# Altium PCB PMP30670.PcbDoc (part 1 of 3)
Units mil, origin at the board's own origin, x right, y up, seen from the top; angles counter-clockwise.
Board outline 5900 x 3950 mil, 4 copper layers (Top Layer, GND, Signal Layer, Bottom Layer), stack 79.834 mil thick; 198 components, 106 nets, 638 pads, 723 vias.
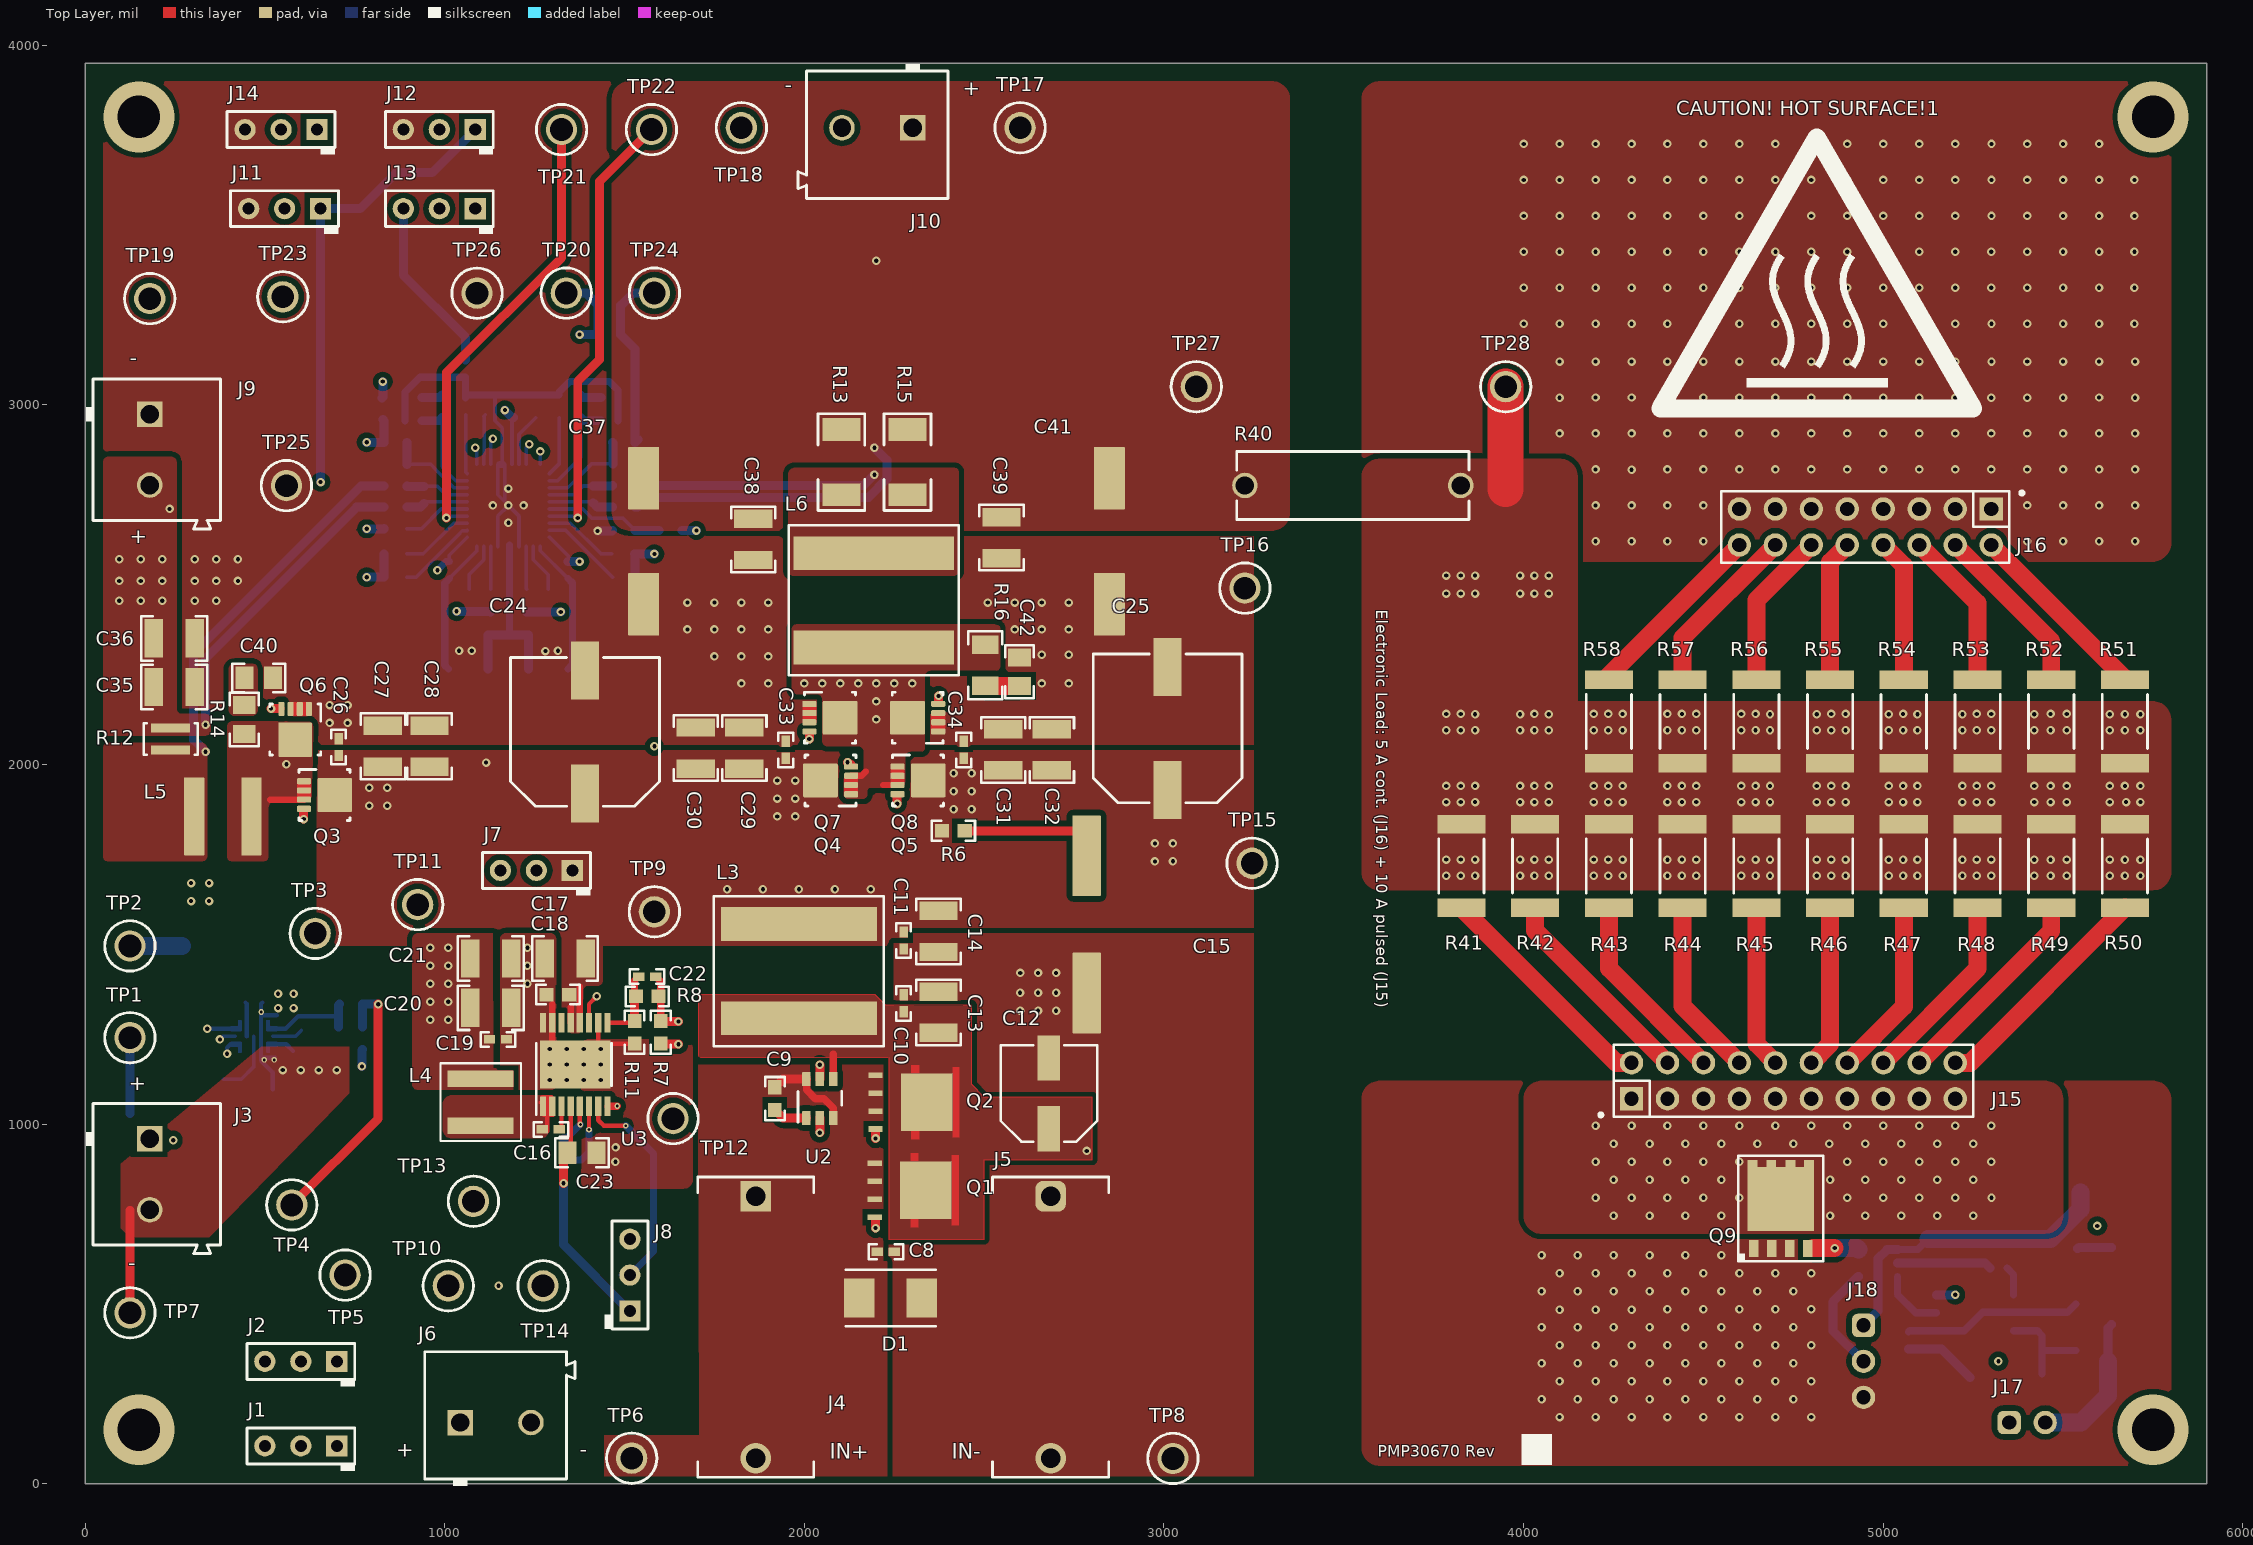
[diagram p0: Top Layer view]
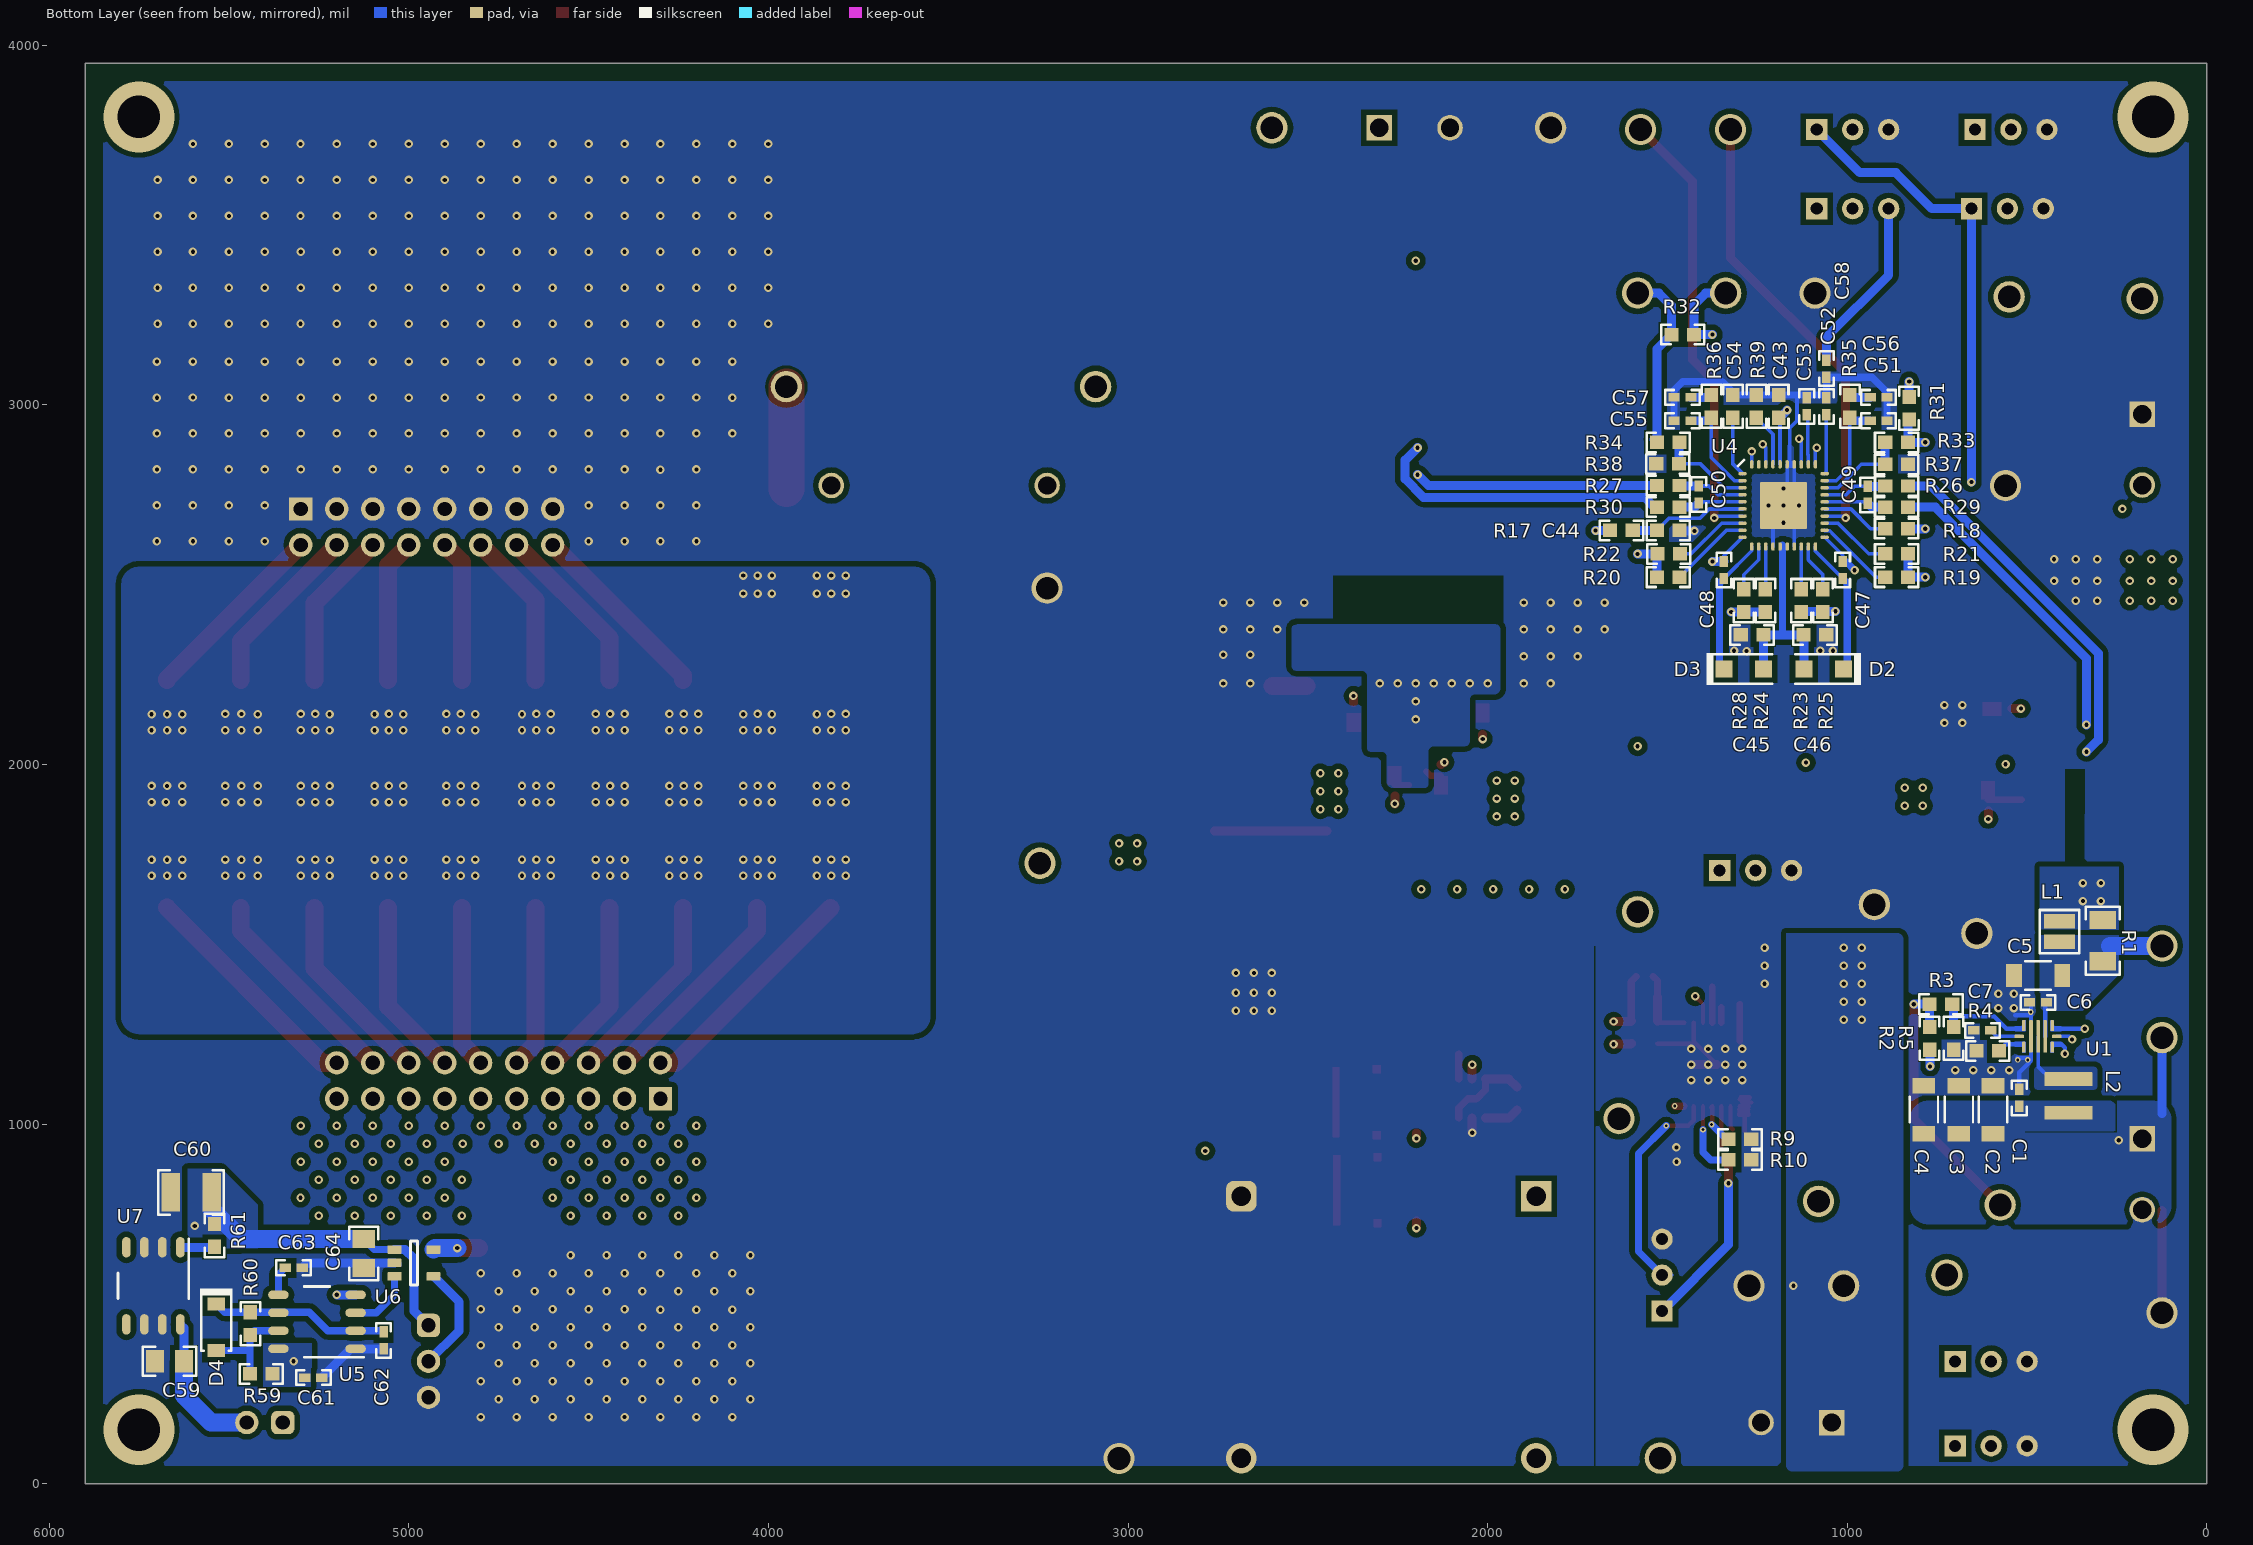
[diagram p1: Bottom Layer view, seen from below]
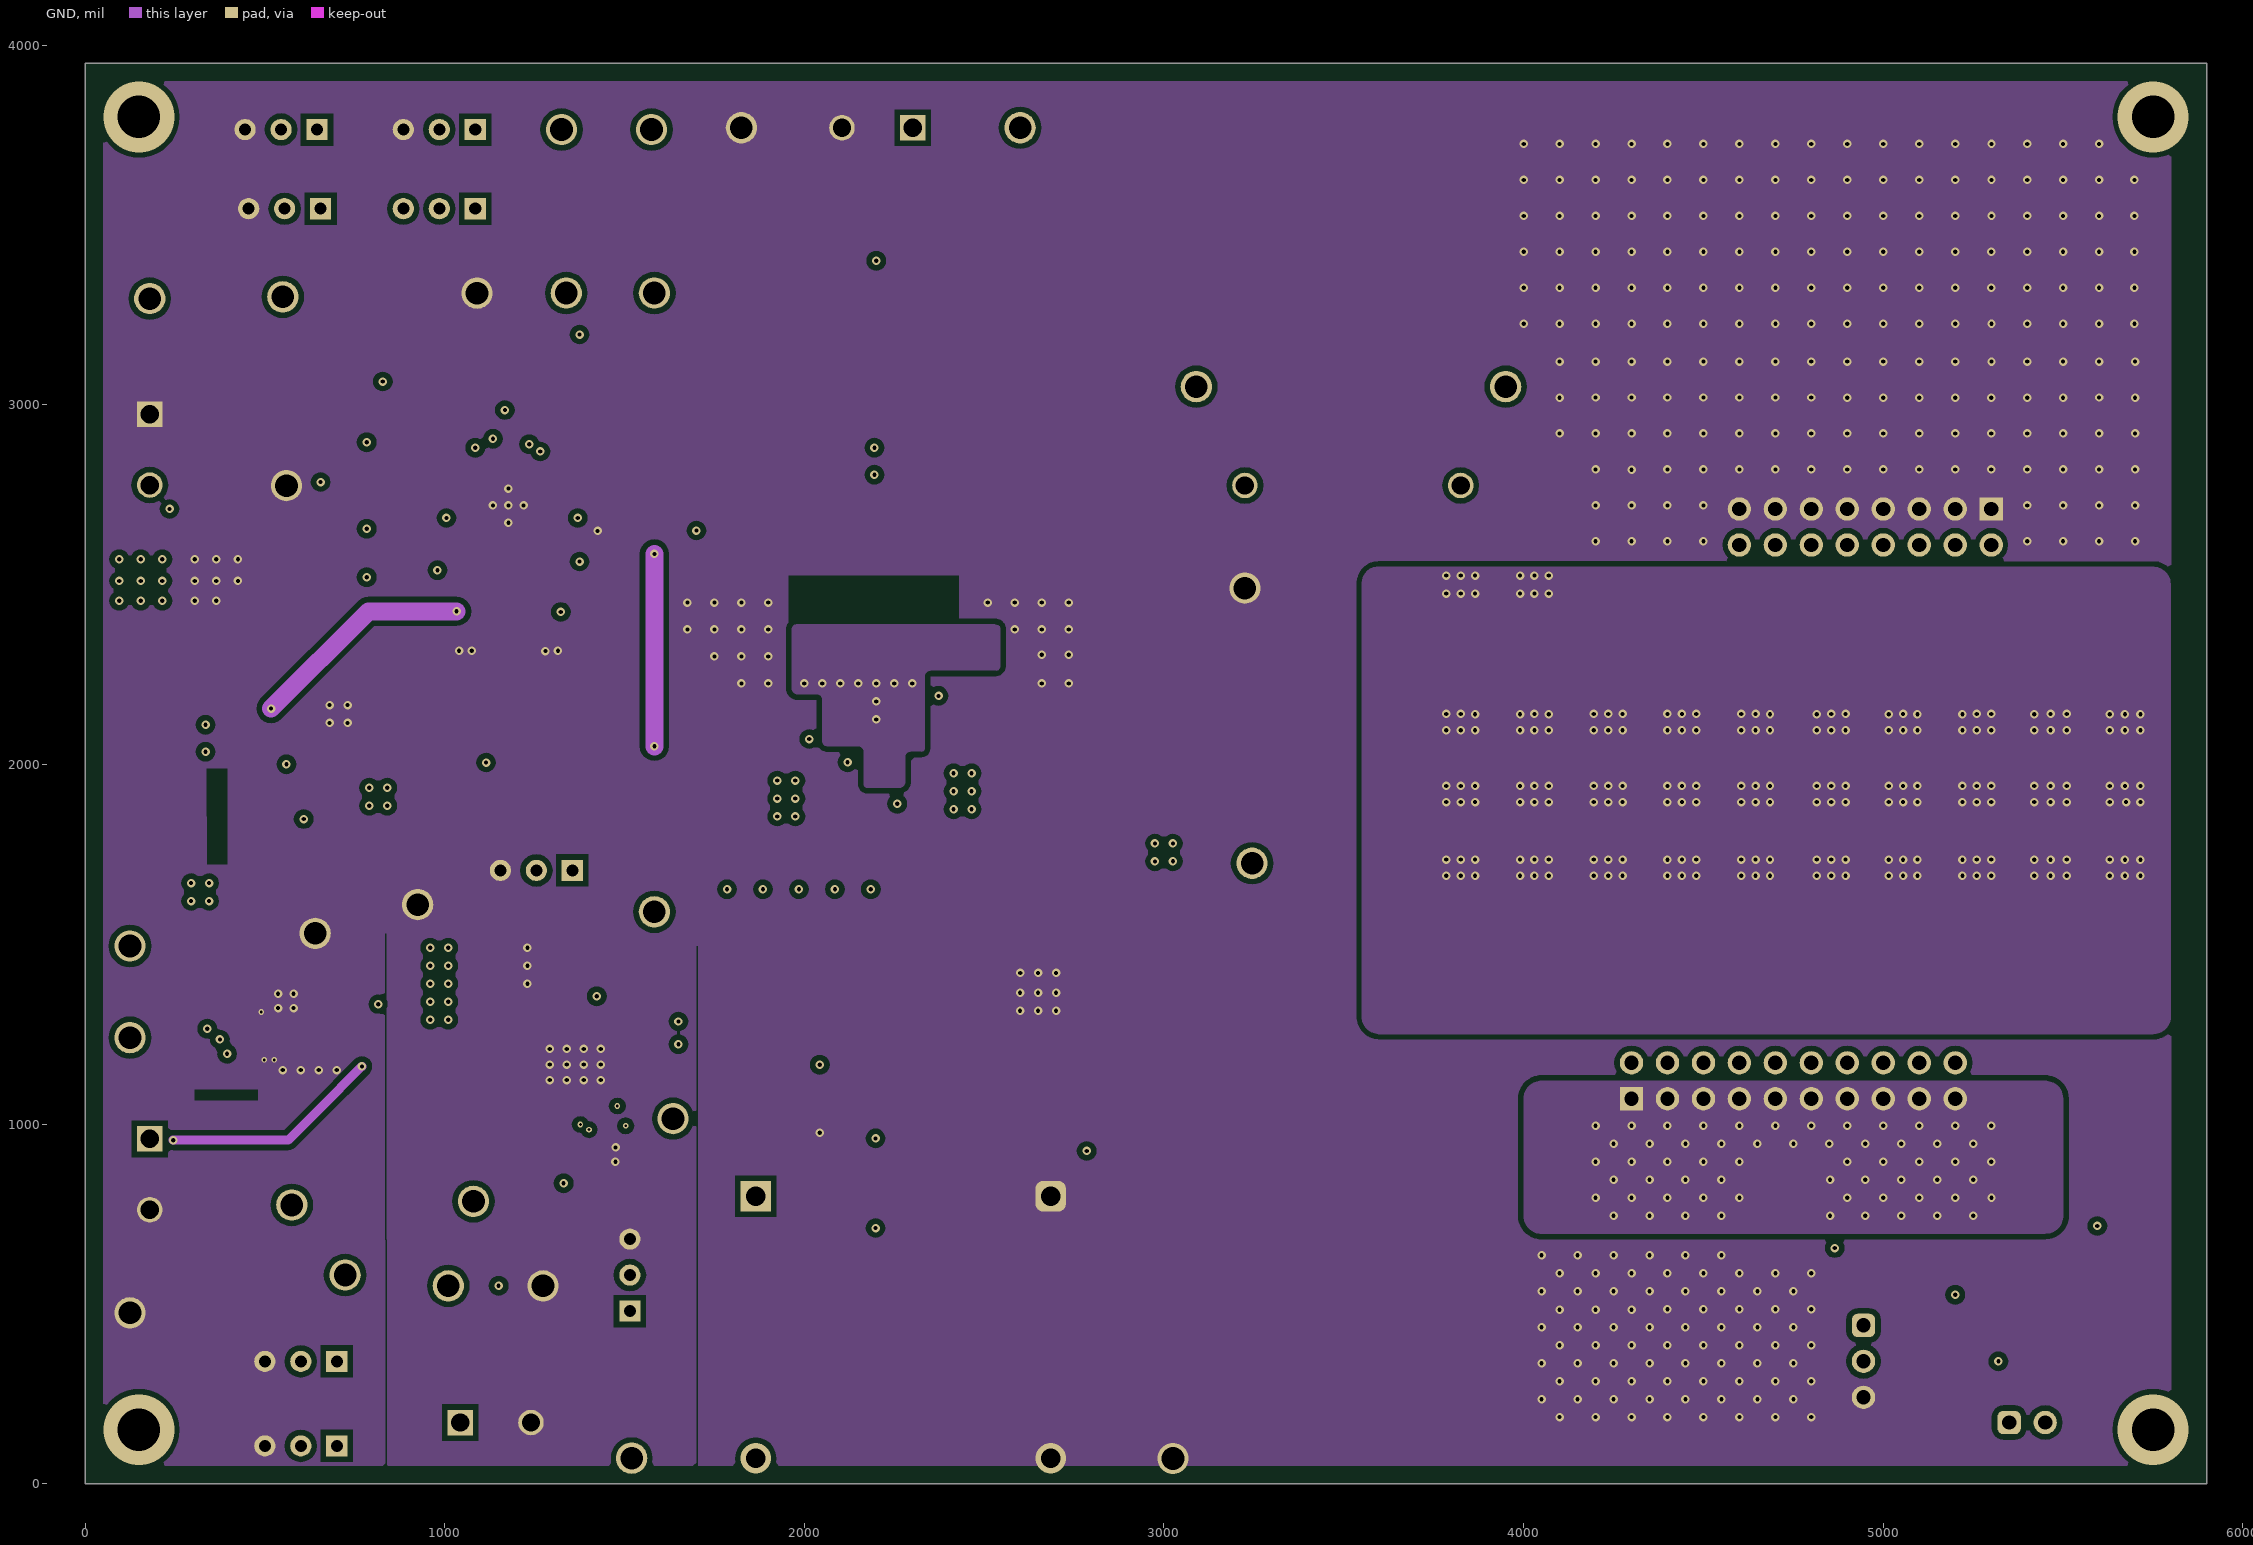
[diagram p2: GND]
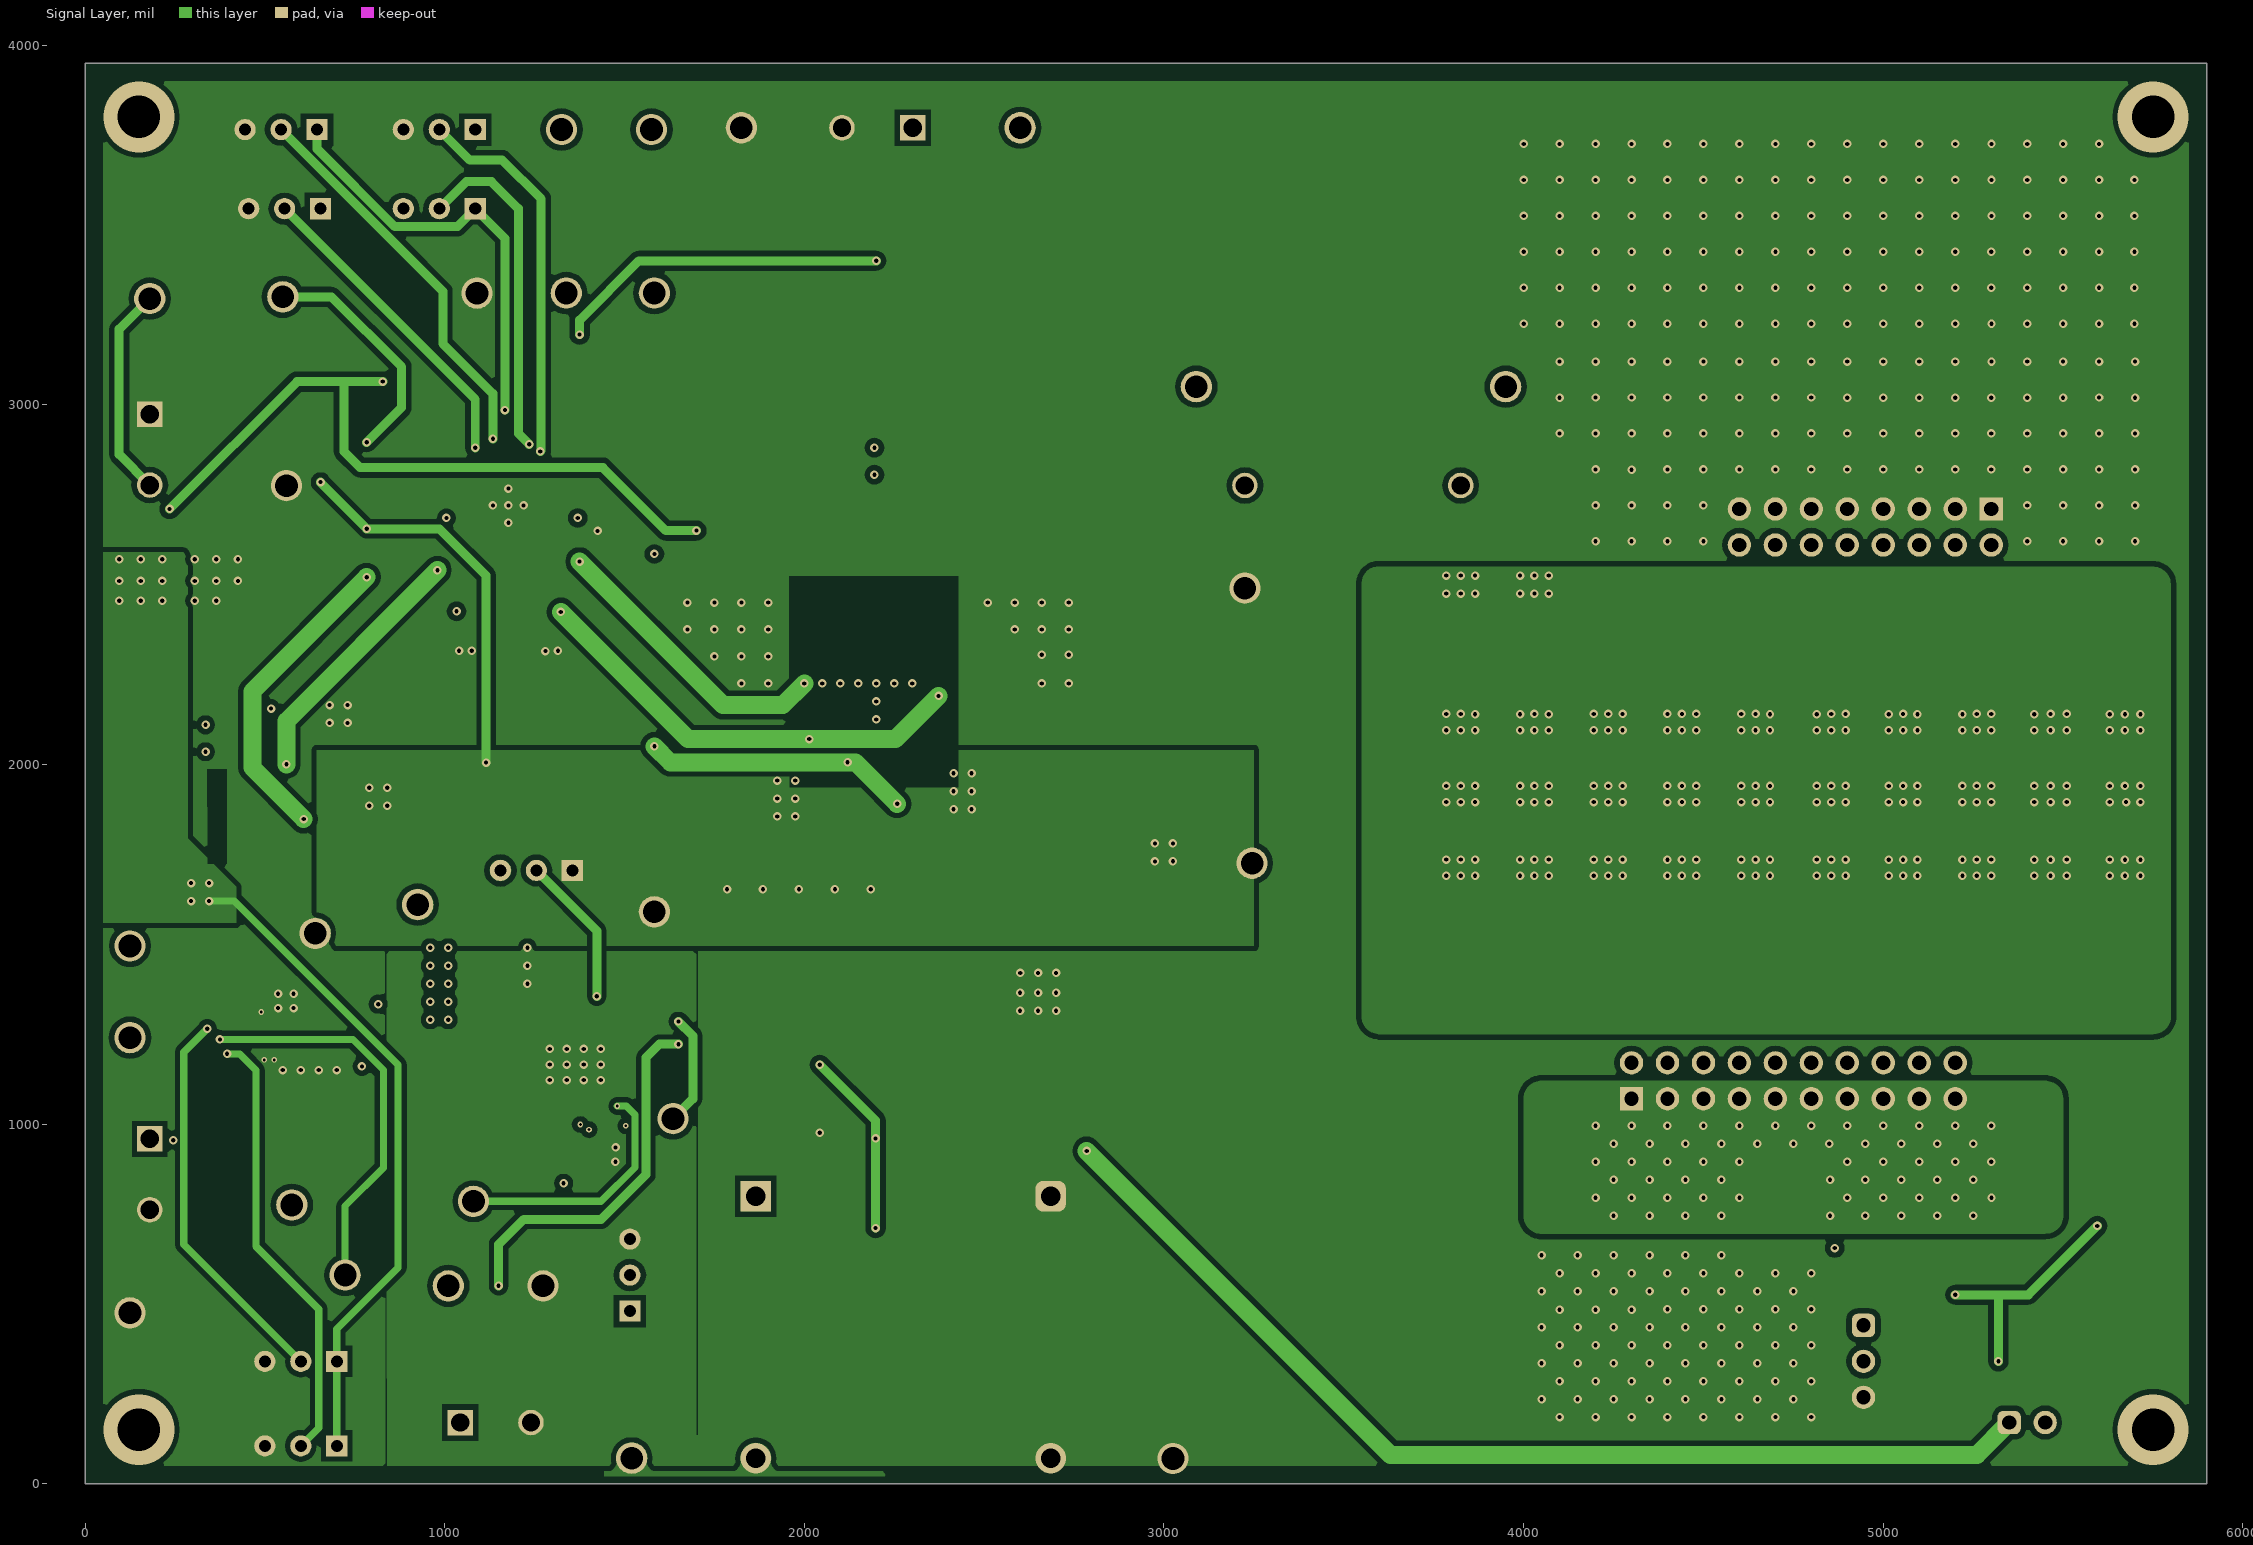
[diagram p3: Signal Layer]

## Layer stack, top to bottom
Top Solder: solder mask 0.4, Solder Resist, Dk 3.5
Top Layer: signal copper 1.4
Dielectric1: core 59.2, FR-4, Dk 4.8
GND: signal copper 1.417
Dielectric 3: prepreg 5, Dk 4.2
Signal Layer: signal copper 1.417
Dielectric 2: core 10, Dk 4.2
Bottom Layer: signal copper 1.4
Bottom Solder: solder mask 0.4, Solder Resist, Dk 3.5

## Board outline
0,0 5900,0 5900,3950 0,3950

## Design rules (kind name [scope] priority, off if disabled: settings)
AcuteAngle [All] p1: minimum=4.50000000000000E+0001 checktracksonly=FALSE
AssemblyTestPointUsage [All] p1: valid=2
Clearance Clearance_Keepouts [((IsTrack Or IsArc) And Not InPoly) And IsFree and IsKeepOut vs ((IsTrack Or IsArc) And Not InPoly) And IsFree and IsKeepOut] p1: gap=0 ignorepadtopadclearanceinfootprint=FALSE
Clearance Clearance_BoardEdge_MountingHoles [OnCopper and InComponentClass('Mounting Holes') vs IsKeepOut] p2: gap=40 ignorepadtopadclearanceinfootprint=FALSE except(0: Arc-Hole Track-Hole SMDPad-Hole THPad-Hole Via-Hole Fill-Hole Poly-Hole Region-Hole Text-Hole)
Clearance Clearance_BoardEdge_Poly [OnCopper and InPoly vs IsKeepOut] p3: gap=25 ignorepadtopadclearanceinfootprint=FALSE except(0: Arc-Hole Track-Hole SMDPad-Hole THPad-Hole Via-Hole Fill-Hole Poly-Hole Region-Hole Text-Hole)
Clearance Clearance_BoardEdge [OnCopper and Not InComponentClass('Logo') and not InComponentClass('FiducialMark') and not InRegion(1000,500,4000,800) and Not IsKeepout vs IsKeepOut] p4: gap=75 ignorepadtopadclearanceinfootprint=FALSE except(0: Arc-Hole Track-Hole SMDPad-Hole THPad-Hole Via-Hole Fill-Hole Poly-Hole Region-Hole Text-Hole)
Clearance Clearance_Poly [InPolygon] p5: gap=15 ignorepadtopadclearanceinfootprint=FALSE except(0: Arc-Hole Track-Hole SMDPad-Hole THPad-Hole Via-Hole Fill-Hole Poly-Hole Region-Hole Text-Hole)
Clearance [All] p6: gap=7.87 ignorepadtopadclearanceinfootprint=FALSE except(0: Arc-Hole Track-Hole SMDPad-Hole THPad-Hole Via-Hole Fill-Hole Poly-Hole Region-Hole Text-Hole)
ComponentClearance ComponentClearance_MountingHoles_FiducialMarks [InComponentClass('Mounting Holes') vs InComponentClass('FiducialMark')] p1: gap=50 collisioncheckmode=3 verticalgap=10 showdistances=FALSE
ComponentClearance ComponentClearance_Shunt [InComponentClass('Header') vs InComponentClass('Shunt')] p2: gap=0 collisioncheckmode=3 verticalgap=0 showdistances=FALSE
ComponentClearance ComponentClearance_Logo [InComponentClass('Logo')] p3: gap=50 collisioncheckmode=3 verticalgap=10 showdistances=FALSE
ComponentClearance ComponentClearance_ScrewToNut [(HasFootprint('NY PMS 440 0025 PH')) vs (HasFootprint('Keystone_1902C'))] p4: gap=5 collisioncheckmode=3 verticalgap=10 showdistances=FALSE
ComponentClearance ComponentClearance_MountingHoles [InComponentClass('Mounting Holes')] p5: gap=250 collisioncheckmode=3 verticalgap=100000 showdistances=FALSE
ComponentClearance ComponentClearance_SmallPassives [HasFootprint('0201*') or HasFootprint('0402*') or HasFootprint('0508') or HasFootprint('0603*') or HasFootprint('0612') or HasFootprint('0805*') or HasFootprint('0815*') or HasFootprint('0830*') or HasFootprint('1206*') or HasFootprint('1210*') or HasFootprint('1808*') or HasFootprint('1812*') or HasFootprint('1825*') or HasFootprint('2010*') or HasFootprint('2220*') or HasFootprint('2225*') or HasFootprint('2512*') or HasFootprint('2728*') or HasFootprint('3518*') vs HasFootprint('0201*') or HasFootprint('0402*') or HasFootprint('0508') or HasFootprint('0603*') or HasFootprint('0612') or HasFootprint('0805*') or HasFootprint('0815*') or HasFootprint('0830*') or HasFootprint('1206*') or HasFootprint('1210*') or HasFootprint('1808*') or HasFootprint('1812*') or HasFootprint('1825*') or HasFootprint('2010*') or HasFootprint('2220*') or HasFootprint('2225*') or HasFootprint('2512*') or HasFootprint('2728*') or HasFootprint('3518*')] p6: gap=20 collisioncheckmode=3 verticalgap=10 showdistances=FALSE
ComponentClearance ComponentClearance_THtoSMT [IsThruComponent vs IsSMTComponent] p7: gap=100 collisioncheckmode=3 verticalgap=30 showdistances=FALSE
ComponentClearance ComponentClearance_THtoTH [IsThruComponent vs IsThruComponent] p8: gap=118.11 collisioncheckmode=3 verticalgap=30 showdistances=FALSE
ComponentClearance [All] p9: gap=40 collisioncheckmode=3 verticalgap=10 showdistances=FALSE
DiffPairsRouting [All] p1: maxlimit=100 minlimit=10 mostfreqgap=10 toplayer_minwidth=15 toplayer_maxwidth=15 toplayer_prefwidth=15 midlayer1_minwidth=15 midlayer1_maxwidth=15 midlayer1_prefwidth=15 midlayer2_minwidth=15 midlayer2_maxwidth=15 midlayer2_prefwidth=15 bottomlayer_minwidth=15 bottomlayer_maxwidth=15 bottomlayer_prefwidth=15 maxuncoupledlength=1000
FabricationTestPointUsage TestPointUsage [All] p1: valid=2 allowmultiple=FALSE
FabricationTestpoint Testpoint [All] p1: side=3 testpointundercomponent=TRUE minsize=40 maxsize=100 preferedsize=60 minholesize=0 maxholesize=40 preferedholesize=32 testpointgrid=1 allowsidetop=TRUE allowsidebottom=TRUE usegrid=TRUE gridtolerance=0.01
FanoutControl Fanout_LCC [IsLCC] p1: bgadir=Out bgaviamode=Centered fanoutstyle=Auto fanoutdirection=Alternating viagrid=1 // Fanout_LCC (Default Rule)
FanoutControl Fanout_BGA [IsBGA] p2: bgadir=Out bgaviamode=Centered fanoutstyle=Auto fanoutdirection=Alternating viagrid=1 // Fanout_BGA (Default Rule)
FanoutControl Fanout_Default [All] p4: bgadir=Out bgaviamode=Centered fanoutstyle=Auto fanoutdirection=Alternating viagrid=1 // Fanout_Default (Default Rule)
FanoutControl Fanout_Small [(CompPinCount < 5)] p5: bgadir=Out bgaviamode=Centered fanoutstyle=Auto fanoutdirection=OutThenIn viagrid=1 // Fanout_Small (Default Rule)
HoleSize [All] p1: absolutevalues=TRUE maxlimit=251 minlimit=11.81 maxpercent=80.000 minpercent=20.000
MinimumAnnularRing MinimumAnnularRing_ThermalPadVias [IsVia and InAnyComponent] p1: minimumring=5.91
MinimumAnnularRing [All] p2: minimumring=5.91
MinimumSolderMaskSliver MinimumSolderMaskSliver_Logo [InComponentClass('Logo') vs InComponentClass('Logo')] p1: minsoldermaskwidth=0.7
MinimumSolderMaskSliver [All] p2: minsoldermaskwidth=3.94
PlaneConnect [All] p1: planeconnectstyle=Relief reliefexpansion=10 reliefentries=4 reliefconductorwidth=10 reliefairgap=10
PolygonConnect [All] p1: connectstyle=Direct reliefconductorwidth=10 reliefentries=4 polygonreliefangle="90 Angle" airgapwidth=10
RoutingVias ThermalPadVias [IsVia and InAnyComponent] p1: holewidth=7.87 width=19.68 viastyle="Through Hole" minholewidth=11.81 minwidth=23.62 maxholewidth=12.99 maxwidth=23.62
RoutingVias [All] p2: holewidth=11.81 width=23.62 viastyle="Through Hole" minholewidth=11.81 minwidth=23.62 maxholewidth=40 maxwidth=65
SilkToBoardRegionClearance [Not ((IsComment or IsDesignator) And (Hide <> 'False')) and not InRegion(1000,500,4000,800)] p1:
SilkToSilkClearance SilkToSilkClearance_Pb-FreeLogo [(HasFootprint('Pb-Free_Overlay_Medium') OR HasFootprint('Pb-Free_Overlay_Small')) vs (HasFootprint('Pb-Free_Overlay_Medium') OR HasFootprint('Pb-Free_Overlay_Small'))] p1: silktosilkclearance=0
SilkToSilkClearance [All] p2: silktosilkclearance=4
SilkToSolderMaskClearance SilkToComonentPadClearance [IsPad and InAnycomponent] p1: minsilkscreentomaskgap=5 clearancetoexposedcopper=TRUE
SilkToSolderMaskClearance "Silk to Solder Mask Opening" [All] p2: minsilkscreentomaskgap=4 clearancetoexposedcopper=FALSE
SolderMaskExpansion [All] p1: expansion=1.97
Width [All] p1: maxlimit=100 minlimit=6 preferedwidth=10 checkconnectedcopper=TRUE
15 further rules are at their usual default settings.

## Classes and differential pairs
component class PMP30670RevA_3: C59 C60 C61 C62 C63 C64 "CAUTION! HOT SURFACE!1" D4 J15 J16 J17 J18 Q9 R40 R41 R42 R43 R44 R45 R46 R47 R48 R49 R50 R51 R52 R53 R54 R55 R56 R57 R58 R59 R60 R61 TP27 TP28 U5 U6 U7
component class PMP30670RevA_2: C24 C25 C26 C27 C28 C29 C30 C31 C32 C33 C34 C35 C36 C37 C38 C39 C40 C41 C42 C43 C44 C47 C48 C49 C50 C51 C52 C53 C54 C55 C56 C57 C58 C60 C61 D2 D3 J9 J10 J11 J12 J13 J14 L5 L6 Q3 Q4 Q5 Q6 Q7 Q8 R12 R13 R14 R15 R16 R17 R18 R19 R20 R21 R22 R23 R24 R25 R26 R27 R28 R29 R30 R31 R32 R33 R34 R35 R36 R37 R38 R39 TP15 TP16 TP17 TP18 TP19 TP20 TP21 TP22 TP23 TP24 TP25 TP26 U4
component class PMP30670RevA_1: C1 C2 C3 C4 C5 C6 C7 C8 C9 C10 C11 C12 C13 C14 C15 C16 C17 C18 C19 C20 C21 C22 C23 D1 J1 J2 J3 J4 J5 J6 J7 J8 L1 L2 L3 L4 Q1 Q2 R1 R2 R3 R4 R5 R6 R7 R8 R9 R10 R11 TP1 TP2 TP3 TP4 TP5 TP6 TP7 TP8 TP9 TP10 TP11 TP12 TP13 TP14 U1 U2 U3
component class Header: J1 J2 J7 J8 J11 J12 J13 J14 J15 J16 J17 J18

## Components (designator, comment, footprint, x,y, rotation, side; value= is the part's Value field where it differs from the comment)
C1 "GRM155R71H104ME14D" 0402 521.81,1072.6 r90 bottom value=0.1uF
C2 "GCM31CR71A226KE02" 1206_180 595,1040 r90 bottom value=22uF
C3 "GCM31CR71A226KE02" 1206_180 690,1040 r90 bottom value=22uF
C4 "GCM31CR71A226KE02" 1206_180 787.18,1040 r90 bottom value=22uF
C5 "GCM31CR71A226KE02" 1206_180 469.65,1413.07 r0 bottom value=22uF
C6 "GRM155R71H104ME14D" 0402 469.65,1338.07 r0 bottom value=0.1uF
C7 "GRM155R71C103KA01D" 0402 624.65,1260.2 r0 bottom value=0.01uF
C8 "GRM155R71H104ME14D" 0402 2226.81,645 r0 top value=0.1uF
C9 "GRM188R71E105KA12D" 0603 1918.07,1070.71 r90 top value=1uF
C10 "GRM155R71H104ME14D" 0402 2275.79,1335.35 r90 top value=0.1uF
C11 "GRM155R71H104ME14D" 0402 2275.79,1510.35 r270 top value=0.1uF
C12 "EEE-FK1H470XP" SM_RADIAL_D8 2680,1085 r90 top value=47uF
C13 "GRM32ER71H106KA12L" 1210_270 2373.07,1310.35 r90 top value=10uF
C14 "GRM32ER71H106KA12L" 1210_270 2373.07,1535.35 r270 top value=10uF
C15 "EEVTG1H221Q" FP-EEVTG1H221Q_RADIAL-Recommended_Land_Pattern 2785,1555 r90 top
C16 "GRM155R71C224KA12D" 0402 1295,985 r180 top value=0.22uF
C17 "GRM32ER71H106KA12L" 1210_270 1335,1460 r180 top value=10uF
C18 "GRM188R71H224KAC4D" 0603 1315,1360 r180 top value=0.22uF
C19 "GRM155R71H104ME14D" 0402 1148.07,1235 r0 top value=0.1uF
C20 "GRM32ER71A226ME20L" 1210_270 1128.03,1323.07 r0 top value=22uF
C21 "GRM32ER71A226ME20L" 1210_270 1128.07,1460 r0 top value=22uF
C22 "GRM1555C1H390JA01D" 0402 1563.07,1410 r180 top value=39pF
C23 "GRM21BR71A105KA01L" 0805_HV 1381.68,920 r0 top value=1uF
C24 "EEH-ZC1H101P" Panasonic_G 1390.16,2090 r90 top value=100uF
C25 "EEH-ZC1H101P" Panasonic_G 3010,2100 r90 top value=100uF
C26 "GRM155R71H104ME14D" 0402 705,2047.98 r90 top value=0.1uF
C27 "GRM32ER71H106KA12L" 1210_270 828.07,2050.35 r90 top value=10uF
C28 "GRM32ER71H106KA12L" 1210_270 958.07,2050.35 r90 top value=10uF
C29 "GRM32ER71H106KA12L" 1210_270 1833.07,2045.35 r90 top value=10uF
C30 "GRM32ER71H106KA12L" 1210_270 1698.07,2045.35 r90 top value=10uF
C31 "GRM32ER71H106KA12L" 1210_270 2553.07,2040.35 r90 top value=10uF
C32 "GRM32ER71H106KA12L" 1210_270 2688.07,2040.35 r90 top value=10uF
C33 "GRM155R71H104ME14D" 0402 1948.07,2040.35 r90 top value=0.1uF
C34 "GRM155R71H104ME14D" 0402 2443.07,2040.35 r90 top value=0.1uF
C35 "GRM32ER71A476ME15L" 1210_270 248.07,2215.35 r0 top value=47uF
C36 "GRM32ER71A476ME15L" 1210_270 248.07,2350.35 r0 top value=47uF
C37 "HHXB160ARA471MJA0G" FP-HHXB160ARA471MJA0G_RADIAL-MFG 1553.07,2620.35 r90 top
C38 "GRM32DR71A106MA01L" 1210_220 1858.07,2625.35 r270 top value=10uF
C39 "GRM32DR71A106MA01L" 1210_220 2548.07,2630.35 r270 top value=10uF
C40 "GRM21AR72E222KW01D" 0805_HV 483.07,2240.35 r0 top value=2200pF
C41 "HHXB160ARA471MJA0G" FP-HHXB160ARA471MJA0G_RADIAL-MFG 2848.07,2620.35 r90 top
C42 "GRM21AR72E222KW01D" 0805_HV 2598.07,2257.56 r90 top value=2200pF
C43 "GRM188R71A474KA61D" 0603 1190.83,2995.35 r270 bottom value=0.47uF
C44 "GRM188Z71C225KE43" 0603 1498.07,2650.35 r180 bottom value=2.2uF
C45 "GRM188Z71C225KE43" 0603 1265,2360 r0 bottom value=2.2uF
C46 "GRM188Z71C225KE43" 0603 1090,2360 r180 bottom value=2.2uF
C47 "GRM155R71C104KA88D" 0402 1013.07,2540.35 r90 bottom value=0.1uF
C48 "GRM155R71C104KA88D" 0402 1343.07,2540.35 r90 bottom value=0.1uF
C49 "GRM155R72A222KA01D" 0402 943.07,2749.41 r270 bottom value=2200pF
C50 "GRM155R72A222KA01D" 0402 1413.07,2750.35 r270 bottom value=2200pF
C51 "GRM1555C1H101JA01D" 0402 913.07,2955.35 r180 bottom value=100pF
C52 "GRM155R71A333KA01D" 0402 1058.07,2995.35 r90 bottom value=0.033uF
C53 "GRM155R71A683KA01D" 0402 1113.07,2995.35 r90 bottom value=0.068uF
C54 "GRM188R71A334KA61D" 0603 1318.07,2995.35 r90 bottom value=0.33uF
C55 "GRM155R71H471KA01D" 0402 1458.07,2955.35 r0 bottom value=470pF
C56 "GRM155R71C103KA01D" 0402 913.07,3020.35 r180 bottom value=0.01uF
C57 "GRM155R71C103KA01D" 0402 1458.07,3020.35 r0 bottom value=0.01uF
C58 "GRM155R71C103KA01D" 0402 1058.07,3100 r270 bottom value=0.01uF
C59 "GRM21BR71H105KA12L" 0805_HV 5665,340 r0 bottom value=1uF
C60 "GRM32ER71C226ME18L" 1210_270 5605,810 r0 bottom value=22uF
C61 "GRM155R71H104ME14D" 0402 5265,295 r180 bottom value=0.1uF
C62 "GRM155R71H104ME14D" 0402 5070,398.5 r270 bottom value=0.1uF
C63 "GRM155R71H104ME14D" 0402 5320,600 r180 bottom value=0.1uF
C64 "GRM21BR71A475KA73L" 0805_HV 5125,640 r270 bottom value=4.7uF
"CAUTION! HOT SURFACE!1" "CAUTION HOT SURFACE" IEC_HotSurface_Large 4815,3365 r0 top
D1 "SMBJ33CA-13-F" SMB-Bi 2240,516.22 r180 top value=33V
D2 "PMEG6010CEH,115" SOD-123F 1065.94,2265 r0 bottom value=60V
D3 "PMEG6010CEH,115" SOD-123F 1288.07,2265 r180 bottom value=60V
D4 "1N4148WFL-G3-08" SOD-123FL 5535,435 r270 bottom value=100V
J1 "800-10-003-10-001000" Mill-Max_800-10-003-10-001000 600,105 r180 top
J2 "800-10-003-10-001000" Mill-Max_800-10-003-10-001000 600,340 r180 top
J3 "691 101 710 002" Wurth_691101710002 180,860 r270 top
J4 "973 582-101" "HIRSCHMANN_973 582-101" 1865,435 r270 top
J5 "973 582-100" "HIRSCHMANN_973 582-100" 2685,435 r270 top
J6 "691 101 710 002" Wurth_691101710002 1141.57,170 r0 top
J7 "800-10-003-10-001000" Mill-Max_800-10-003-10-001000 1255,1705 r180 top
J8 "800-10-003-10-001000" Mill-Max_800-10-003-10-001000 1515,580 r90 top
J9 "691 101 710 002" Wurth_691101710002 180,2875 r270 top
J10 "691 101 710 002" Wurth_691101710002 2203.07,3770 r180 top
J11 "800-10-003-10-001000" Mill-Max_800-10-003-10-001000 555,3545 r180 top
J12 "800-10-003-10-001000" Mill-Max_800-10-003-10-001000 985,3765 r180 top
J13 "800-10-003-10-001000" Mill-Max_800-10-003-10-001000 985,3545 r180 top
J14 "800-10-003-10-001000" Mill-Max_800-10-003-10-001000 545,3765 r180 top
J15 "TSW-110-07-G-D" TSW-110-07-G-D 4750,1120 r0 top
J16 "TSW-108-07-G-D" TSW-108-07-G-D 4950,2660 r180 top
J17 "TSW-102-07-G-S" TSW-102-07-G-S 5400,170 r0 top
J18 "TSW-103-07-G-S" TSW-103-07-G-S 4945,340 r270 top
L1 "XPL2010-201MLB" XPL2010 410,1535 r270 bottom value=200nH
L2 "XEL4020-561MEB" XEL4020 384.65,1078.07 r270 bottom value=560nH
L3 "XAL1060-472MEB" XAL1060 1985,1425 r90 top value=4.7uH
L4 "XEL5030-222MEB" XAL5030 1100,1060.71 r90 top value=2.2uH
L5 "XAL6060-153MEB" XAL6060 383.07,1855.35 r0 top value=15uH
L6 "XAL1010-222MEB" XAL1010 2193.07,2455.87 r90 top value=2.2uH
Q1 "SQJA60EP" PowerPAK_SO-8L 2306.42,815.71 r0 top value=60V
Q2 "SQJA60EP" PowerPAK_SO-8L 2308.5,1060.71 r0 top value=60V
Q3 "IPZ40N04S5L-7R4" PG-TSDSON-8-32 666.1,1914.68 r0 top value=40V
Q4 "IPZ40N04S5L-7R4" PG-TSDSON-8-32 2073.07,1955.35 r180 top value=40V
Q5 "IPZ40N04S5L-7R4" PG-TSDSON-8-32 2316.3,1955.43 r0 top value=40V
Q6 "IPZ40N04S5L-7R4" PG-TSDSON-8-32 584.33,2096.97 r270 top value=40V
Q7 "IPZ40N04S5L-2R8" PG-TSDSON-8-32 2071.1,2129.68 r0 top value=40V
Q8 "IPZ40N04S5L-2R8" PG-TSDSON-8-32 2315.16,2129.69 r180 top value=40V
Q9 "BSC093N04LS G" PG-TDSON-8 4715,765 r90 top value=40V
R1 "ERJ-8GEY0R00V" 1206 290,1510 r270 bottom value=0
R2 "CRCW060349R9FKEA" 0603 771.14,1238.07 r270 bottom value=49.9
R3 "CRCW060339K2FKEA" 0603 739.65,1333.07 r0 bottom value=39.2k
R4 "CRCW06039K09FKEA" 0603 609.65,1203.07 r180 bottom value=9.09k
R5 "CRCW060347K0FKEA" 0603 704.65,1238.07 r90 bottom value=47.0k
R6 "ERJ-3RSFR12V" 0603 2414.57,1815.35 r180 top value=0.12
R7 "CRCW060349R9FKEA" 0603 1600.67,1255 r270 top value=49.9
R8 "CRCW060346K4FKEA" 0603 1563.07,1355 r0 top value=46.4k
R9 "CRCW06037K68FKEA" 0603 1298.5,958 r0 bottom value=7.68k
R10 "CRCW060310K0FKEA" 0603 1298.5,900 r0 bottom value=10.0k
R11 "CRCW060320K0FKEA" 0603 1528.07,1255 r90 top value=20.0k
R12 "PRL1632-R013-F-T1" 0612 238.07,2070.35 r270 top value=0.013
R13 "CSNL2010FT5L00" 2010 2103.07,2840.35 r90 top value=0.005
R14 "CRCW08051R00JNEA" 0805_HV 443.07,2124.92 r270 top value=1.0
R15 "CSNL2010FT5L00" 2010 2286.81,2840.35 r90 top value=0.005
R16 "CRCW12061R00FKEA" 1206 2503.07,2275.35 r90 top value=1.00
R17 "CRCW06031R00FKEA" 0603 1628.07,2650.35 r0 bottom value=1.00
R18 "ERJ-3GEY0R00V" 0603 863.07,2655.35 r0 bottom value=0
R19 "ERJ-3GEY0R00V" 0603 863.07,2520.35 r0 bottom value=0
R20 "ERJ-3GEY0R00V" 0603 1498.07,2520.35 r0 bottom value=0
R21 "ERJ-3GEY0R00V" 0603 863.07,2585.35 r0 bottom value=0
R22 "ERJ-3GEY0R00V" 0603 1496.57,2585.35 r0 bottom value=0
R23 "ERJ-3GEY0R00V" 0603 1128.07,2455.35 r270 bottom value=0
R24 "ERJ-3GEY0R00V" 0603 1228.07,2455.35 r270 bottom value=0
R25 "ERJ-3GEY0R00V" 0603 1068.07,2455.35 r270 bottom value=0
R26 "CRCW060349R9FKEA" 0603 863.07,2773.98 r180 bottom value=49.9
R27 "CRCW060349R9FKEA" 0603 1498.07,2775.35 r180 bottom value=49.9
R28 "ERJ-3GEY0R00V" 0603 1288.07,2455.35 r270 bottom value=0
R29 "ERJ-3GEY0R00V" 0603 863.07,2715.35 r0 bottom value=0
R30 "ERJ-3GEY0R00V" 0603 1498.07,2715.35 r0 bottom value=0
R31 "CRCW060349R9FKEA" 0603 828.07,2990.35 r90 bottom value=49.9
R32 "CRCW060349R9FKEA" 0603 1457.6,3195 r180 bottom value=49.9
R33 "CRCW060373K2FKEA" 0603 863.07,2895.35 r180 bottom value=73.2k
R34 "CRCW060345K3FKEA" 0603 1498.07,2895.35 r0 bottom value=45.3k
R35 "CRCW06035K90FKEA" 0603 993.07,2995.35 r270 bottom value=5.90k
R36 "CRCW060313K7FKEA" 0603 1378.07,2995.35 r270 bottom value=13.7k
R37 "CRCW060310K0FKEA" 0603 863.07,2834.06 r0 bottom value=10.0k
R38 "CRCW060310K0FKEA" 0603 1499.57,2835.35 r180 bottom value=10.0k
R39 "CRCW060354K9FKEA" 0603 1253.07,2995.35 r270 bottom value=54.9k
R40 "OAR3R010FLF" PWR4412-2S-3W 3525,2775.35 r0 top value=0.01
R41 "CRCW251230R0JNEG" 2512 3827,1717.2 r90 top value=30
R42 "CRCW251230R0JNEG" 2512 4032,1717.2 r90 top value=30
R43 "CRCW251230R0JNEG" 2512 4237,1717.2 r90 top value=30
R44 "CRCW251230R0JNEG" 2512 4442,1717.2 r90 top value=30
R45 "CRCW251230R0JNEG" 2512 4647,1717.2 r90 top value=30
R46 "CRCW251230R0JNEG" 2512 4852,1717.2 r90 top value=30
R47 "CRCW251230R0JNEG" 2512 5057,1717.2 r90 top value=30
R48 "CRCW251230R0JNEG" 2512 5262,1717.2 r90 top value=30
R49 "CRCW251230R0JNEG" 2512 5467,1717.2 r90 top value=30
R50 "CRCW251230R0JNEG" 2512 5672,1717.44 r90 top value=30
R51 "CRCW251212R1FKEG" 2512 5672,2119 r270 top value=12.1
R52 "CRCW251212R1FKEG" 2512 5467,2119 r270 top value=12.1
R53 "CRCW251212R1FKEG" 2512 5262,2119 r270 top value=12.1
R54 "CRCW251212R1FKEG" 2512 5057,2119 r270 top value=12.1
R55 "CRCW251212R1FKEG" 2512 4852,2119 r270 top value=12.1
R56 "CRCW251212R1FKEG" 2512 4647,2119 r270 top value=12.1
R57 "CRCW251212R1FKEG" 2512 4442,2119 r270 top value=12.1
R58 "CRCW251212R1FKEG" 2512 4237,2119 r270 top value=12.1
R59 "CRCW060371K5FKEA" 0603 5410,305 r180 bottom value=71.5k
R60 "CRCW060371K5FKEA" 0603 5440,445 r270 bottom value=71.5k
R61 "CRCW06031R00JNEA" 0603 5540,690 r90 bottom value=1.0
TP1 "5010" Keystone5010 125,1240 r0 top
TP2 "5010" Keystone5010 125,1495 r0 top
TP3 "5011" Keystone5011 640,1530 r0 top
TP4 "5014" Keystone5014 575,775 r0 top
TP5 "5012" Keystone5012 723.19,580 r0 top
TP6 "5010" Keystone5010 1520,70.83 r0 top
TP7 "5011" Keystone5011 125,475 r0 top
TP8 "5011" Keystone5011 3025,70 r0 top
TP9 "5010" Keystone5010 1583.07,1590 r0 top
TP10 "5010" Keystone5010 1010,550 r0 top
TP11 "5011" Keystone5011 925,1610 r0 top
TP12 "5014" Keystone5014 1635,1015 r0 top
TP13 "5012" Keystone5012 1080,785 r0 top
TP14 "5011" Keystone5011 1273.5,550 r0 top
TP15 "5010" Keystone5010 3245,1725 r0 top
TP16 "5011" Keystone5011 3225,2490 r0 top
TP17 "5010" Keystone5010 2600,3770 r0 top
TP18 "5011" Keystone5011 1825,3770 r0 top
TP19 "5010" Keystone5010 180,3295 r0 top
TP20 "5010" Keystone5010 1338.07,3310.35 r0 top
TP21 "5012" Keystone5012 1325,3765 r0 top
TP22 "5012" Keystone5012 1575,3765 r0 top
TP23 "5014" Keystone5014 550,3300 r0 top
TP24 "5014" Keystone5014 1583.07,3310.35 r0 top
TP25 "5011" Keystone5011 560,2775 r0 top
TP26 "5011" Keystone5011 1090,3310 r0 top
TP27 "5013" Keystone5013 3090,3050 r0 top
TP28 "5013" Keystone5013 3950,3050 r0 top
U1 "TPS62810QWRWYRQ1" RWY0009A 469.65,1243.46 r270 bottom
U2 "LM74700QDBVRQ1" DBV0006A_N 2043.07,1070.71 r90 top
U3 "LM63635DQPWPTQ1" PWP0016K_N 1363.07,1165.35 r90 top
U4 "LM5143QRWGRQ1" RWG0040A 1177.24,2719.88 r180 bottom
U5 "LMC555CM/NOPB" D0008A_N 5255,450 r0 bottom
U6 "UCC27517DBVR" DBV0005A_N 4985,613.62 r180 bottom
U7 "TL750L05CD" D0008A_N 5710,550 r270 bottom

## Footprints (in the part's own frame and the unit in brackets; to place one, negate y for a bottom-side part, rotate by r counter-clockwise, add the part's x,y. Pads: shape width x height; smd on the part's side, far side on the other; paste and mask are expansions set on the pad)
0402 [mm] "0402 from SM-752 data"
  rect 0.8x0.6 smd: 1(-0.6,0) 2(0.6,0)
  silkscreen extent -1.22,-0.52 1.22,0.52, body extent -0.55,-0.3 0.55,0.3, height 0.6
0603 [mm] "0603 from SM-752 data"
  rect 1x0.95 smd: 1(-0.8,0) 2(0.8,0)
  silkscreen extent -1.52,-0.69 1.52,0.69, body extent -0.87,-0.47 0.87,0.47, height 1
0612 [mm] "Panasonic recommended land pattern, fb97d03ed01.pdf dated April 2008"
  rect 0.65x2.75 smd: 1(-0.775,0) 2(0.775,0)
  silkscreen extent -1.1,-1.9 1.1,1.9, body extent -0.9,-1.7 0.9,1.7, height 0.85
0805_HV [mil] "0805 with 30mil clearance between pads"
  rect 50x63 smd: 1(-40,0) 2(40,0)
  silkscreen extent -74,-40 74,40, body extent -43,-29 43,29, height 57
1206 [mm] "1206 from SM-752 data"
  rect 1.3x1.85 smd: 1(-1.45,0) 2(1.45,0)
  silkscreen extent -2.4,-1.21 2.4,1.21, body extent -1.7,-0.9 1.7,0.9, height 1.35
1206_180 [mm] "1206_180"
  rect 1.1x1.6 smd: 1(-1.7,0) 2(1.7,0)
  silkscreen extent -0.9,-1 0.9,1, body extent -1.75,-0.95 1.75,0.95, height 1.8
1210_220 [mm] "1210"
  rect 1.3x2.7 smd: 1(-1.45,0) 2(1.45,0)
  silkscreen extent -2.32,-1.57 2.32,1.57, body extent -1.7,-1.35 1.7,1.35, height 2.2
1210_270 [mm] "1210"
  rect 1.3x2.7 smd: 1(-1.45,0) 2(1.45,0)
  silkscreen extent -2.32,-1.57 2.32,1.57, body extent -1.7,-1.35 1.7,1.35, height 2.7
2010 [mm] "Chip Capacitor, Body 5.08x2.54mm, IPC Medium Density"
  rect 1.6x2.7 smd: 1(-2.3,0) 2(2.3,0)
  silkscreen extent -3.42,-1.65 3.42,1.65, body extent -2.73,-1.45 2.73,1.45, height 1.66
2512 [mm] "Chip Resistor, Body 6.3x3.2mm, IPC Medium Density"
  rect 1.3x3.4 smd: 1(-2.95,0) 2(2.95,0)
  silkscreen extent -1.9,-1.6 1.9,1.6, body extent -3.22,-1.67 3.22,1.67, height 0.71
D0008A_N [mm] "SOIC, 8-Leads, Body 4.9x3.9mm, Pitch 1.27mm, IPC Medium Density"
  oval 1.45x0.6 smd: 1(-2.725,1.905) 2(-2.725,0.635) 3(-2.725,-0.635) 4(-2.725,-1.905) 5(2.725,-1.905) 6(2.725,-0.635) 7(2.725,0.635) 8(2.725,1.905)
  silkscreen extent -3.3,-2.5 0.9,2.5, body extent -3,-2.45 3,2.45, height 1.63
DBV0005A_N [mm] "SOT23, 5-Leads, Body 2.9x1.6mm, Pitch 0.95mm, Lead Span 2.8mm, IPC Medium Density"
  rrect17% 1x0.6 smd: 1(-1.375,0.95) 2(-1.375,0) 3(-1.375,-0.95) 4(1.375,-0.95) 5(1.375,0.95)
  silkscreen extent -0.25,-1.55 0.25,1.55, body extent -1.42,-1.46 1.42,1.46, height 1.09
DBV0006A_N [mm] "SOT23, 6-Leads, Body 2.9x1.6mm, Pitch 0.95mm, Lead Span 2.8mm, IPC Medium Density"
  rrect17% 1x0.6 smd: 1(-1.375,0.95) 2(-1.375,0) 3(-1.375,-0.95) 4(1.375,-0.95) 5(1.375,0) 6(1.375,0.95)
  silkscreen extent -1.68,-1.55 0.5,1.55, body extent -1.42,-1.46 1.42,1.46, height 1.12
FP-EEVTG1H221Q_RADIAL-Recommended_Land_Pattern [mm]
  rrect5% 5.7x2 smd paste+0 mask+0: 1(-4.85,0) 2(4.85,0)
  body extent -7.95,-7.1 7.95,7.1, height 0.25
FP-HHXB160ARA471MJA0G_RADIAL-MFG [mm]
  rrect5% 4.4x2.2 smd paste+0 mask+0: 1(-4.45,0) 2(4.45,0)
  body extent -6.9,-5.5 6.9,5.5, height 0.25
"HIRSCHMANN_973 582-100" [mil] "Hirschmann Automation and Control GmbH"
  rrect50% 85x85 hole 55: 1(-364.17,0)
  round 85 hole 55: 2(364.17,0)
  silkscreen extent -417,-161 417,161, body extent -414,-157 413,157, height 413
"HIRSCHMANN_973 582-101" [mil] "Hirschmann Automation and Control GmbH"
  rect 85x85 hole 55: 1(-364.17,0)
  round 85 hole 55: 2(364.17,0)
  silkscreen extent -417,-161 417,161, body extent -414,-157 413,157, height 413
IEC_HotSurface_Large [mil]
  silkscreen extent -435,-375 435,378
Keystone5010 [mil] "Keystone Multipurpose loops"
  round 87 hole 63: 1(0,0)
  silkscreen extent -70,-70 70,70, body extent -63,-63 63,62, height 319
Keystone5011 [mil] "Keystone Multipurpose loops"
  round 87 hole 63: 1(0,0)
  silkscreen extent -70,-70 70,70, body extent -63,-63 63,62, height 319
Keystone5012 [mil] "Keystone Multipurpose loops"
  round 87 hole 63: 1(0,0)
  silkscreen extent -70,-70 70,70, body extent -63,-63 63,62, height 319
Keystone5013 [mil] "Keystone Multipurpose loops"
  round 87 hole 63: 1(0,0)
  silkscreen extent -70,-70 70,70, body extent -63,-63 63,62, height 319
Keystone5014 [mil] "Keystone Multipurpose loops"
  round 87 hole 63: 1(0,0)
  silkscreen extent -70,-70 70,70, body extent -63,-63 63,62, height 319
Mill-Max_800-10-003-10-001000 [mm] "Mill-Max"
  rect 1.5x1.5 hole 0.85: 1(-2.54,0)
  round 1.5 hole 0.85: 2(0,0) 3(2.54,0)
  silkscreen extent -3.81,-1.27 3.81,1.78, body extent -3.81,-1.27 3.81,1.27, height 8.13
Panasonic_G [mm] "SMD, 2-Leads, Dia 10mm"
  rect 4.1x2 smd: 1(-4.35,0) 2(4.35,0)
  silkscreen extent -5.25,-5.25 5.25,5.25, body extent -5.25,-5.25 5.25,5.25, height 10.51
PG-TDSON-8 [mm] "Infineon recommended land pattern"
  rect 1.2x0.65 smd: 1(-2.825,1.905) 2(-2.825,0.635) 3(-2.825,-0.635) 4(-2.825,-1.905)
  rect 0.5x0.7 smd: 5(3.175,-2) 6(3.175,-0.675) 7(3.175,0.675) 8(3.175,2)
  rect 4.5x4.7 smd paste-2.25: 9(0.675,0)
  silkscreen extent -3.74,-3 3.74,3, body extent -3.18,-2.9 3.17,2.9, height 1.1
PG-TSDSON-8-32 [mm] "SMD, 8-Leads, Body 3.3x3.3mm"
  rrect45% 1x0.44 smd paste-1 mask-0.05: 1(-1.45,0.975) 2(-1.45,0.325) 3(-1.45,-0.325) 4(-1.45,-0.975) 5(1.45,-0.975) 6(1.45,-0.325) 7(1.45,0.325) 8(1.45,0.975)
  rrect6% 1.71x2.29 on Top Solder: 9(0.395,0)
  rrect8% 2.46x2.39 smd paste-2 mask-2: 9(0.72,0)
  rrect42% 0.3x0.24 on Top Paste: ""(-1.695,-0.325) ""(-1.695,0.325) ""(-1.695,0.975)
  rrect42% 0.7x0.24 on Top Paste: ""(-1.5,-0.975)
  rrect29% 0.35x0.67 on Top Paste: ""(-1.225,0.76) ""(-1.22,-0.11)
  rrect42% 1.4x0.24 on Top Paste: ""(0.35,-0.975) ""(0.35,0.975)
  rrect9% 1.4x1.09 on Top Paste: ""(0.35,0)
  rrect42% 0.6x0.24 on Top Paste: ""(1.55,-0.975) ""(1.55,-0.325) ""(1.55,0.325) ""(1.55,0.975)
  Top Layer region: -1.95,-0.325 -0.95,-0.325 -0.95,1 -1.95,1
  silkscreen extent -1.8,-1.8 1.8,1.8, body extent -1.7,-1.7 1.7,1.7, height 1.15
PowerPAK_SO-8L [mm] "based on Vishay recommended land pattern Document 63818 Feb 7, 2012"
  rect 1x0.41 smd: 1(-2.805,1.905) 2(-2.805,0.635) 3(-2.805,-0.635) 4(-2.805,-1.905)
  rect 3.63x4.061 smd: 5(0.805,0)
  Top Layer region: 2.615,-2.5 3.125,-2.5 3.125,2.5 2.615,2.5
  Top Layer region: -0.298,2.03 0.297,2.03 0.297,2.64 -0.298,2.64
  Top Layer region: -0.297,-2.64 0.298,-2.64 0.298,-2.03 -0.297,-2.03
  body extent -3.07,-2.57 3.08,2.57, height 1.21
PWP0016K_N [mm] "TSSOP-16"
  rrect22% 1.4x0.45 smd: 1(-2.95,2.275) 2(-2.95,1.625) 3(-2.95,0.975) 4(-2.95,0.325) 5(-2.95,-0.325) 6(-2.95,-0.975) 7(-2.95,-1.625) 8(-2.95,-2.275) 9(2.95,-2.275) 10(2.95,-1.625) 11(2.95,-0.975) 12(2.95,-0.325) 13(2.95,0.325) 14(2.95,0.975) 15(2.95,1.625) 16(2.95,2.275)
  rrect3% 3.4x5 smd paste-1.7 mask-1.7: 17(0,0)
  rrect4% 2.46x2.31 on Top Paste: 17(0,0)
  rrect4% 2.46x2.31 on Top Solder: 17(0,0)
  silkscreen extent -3.55,-2.55 1.5,2.75, body extent -3.21,-2.5 3.21,2.5, height 1
PWR4412-2S-3W [mm] "Bourns 3W bare metal element resistor"
  round 1.8 hole 1.3: 1(-7.62,0) 2(7.62,0)
  silkscreen extent -8.2,-2.4 8.2,2.4, body extent -8.12,-2.4 8.12,2.4, height 25.42
RWG0040A [mm] "QFN, 40-Leads, Body 6x6mm, Pitch 0.5mm, Thermal Pad 3.3 x 3.3mm, TI Recommended"
  rrect7% 1.43x1.43 on Bottom Paste: 0(-0.815,-0.815) 0(-0.815,0.815) 0(0.815,-0.815) 0(0.815,0.815)
  rrect100% 0.6x0.25 smd: 1(-2.9,2.25) 2(-2.9,1.75) 3(-2.9,1.25) 4(-2.9,0.75) 5(-2.9,0.25) 6(-2.9,-0.25) 7(-2.9,-0.75) 8(-2.9,-1.25) 9(-2.9,-1.75) 10(-2.9,-2.25) 21(2.9,-2.25) 22(2.9,-1.75) 23(2.9,-1.25) 24(2.9,-0.75) 25(2.9,-0.25) 26(2.9,0.25) 27(2.9,0.75) 28(2.9,1.25) 29(2.9,1.75) 30(2.9,2.25)
  rrect100% 0.25x0.6 smd: 11(-2.25,-2.9) 12(-1.75,-2.9) 13(-1.25,-2.9) 14(-0.75,-2.9) 15(-0.25,-2.9) 16(0.25,-2.9) 17(0.75,-2.9) 18(1.25,-2.9) 19(1.75,-2.9) 20(2.25,-2.9) 31(2.25,2.9) 32(1.75,2.9) 33(1.25,2.9) 34(0.75,2.9) 35(0.25,2.9) 36(-0.25,2.9) 37(-0.75,2.9) 38(-1.25,2.9) 39(-1.75,2.9) 40(-2.25,2.9)
  rrect3% 3.3x3.3 smd paste-1.65: 41(0,0)
  silkscreen extent -3.21,2.78 -2.79,3.2, body extent -3,-3 3,3, height 0.86
RWY0009A [mm] "VQFN-HR-9"
  rrect40% 0.775x0.25 smd paste-0.2: 1(-0.761,1) 5(-0.761,-1) 7(0.761,-1) 8(0.761,1)
  rrect40% 1.05x0.25 on Bottom Paste: 2(-0.625,0.5) 2(0.625,0.5) 3(-0.625,0) 3(0.625,0) 4(-0.625,-0.5) 4(0.625,-0.5)
  rrect40% 2.3x0.25 smd paste-0.5: 2(0,0.5) 3(0,0) 4(0,-0.5)
  rrect40% 0.25x0.65 smd: 6(0,-1.325) 9(0,1.325)
  Top Layer region: -1.1,-1.125 -1.119,-1.121 -1.135,-1.11 -1.146,-1.094 -1.15,-1.075 -1.15,-1.075 -1.15,-0.925 -1.146,-0.906 -1.135,-0.89 -1.119,-0.879 -1.1,-0.875 -1.1,-0.875 -0.425,-0.875 -0.406,-0.879 -0.39,-0.89 -0.379,-0.906 -0.375,-0.925 -0.375,-0.925 -0.375,-1.6 -0.379,-1.619 -0.39,-1.635 -0.406,-1.646 -0.425,-1.65 -0.425,-1.65 -0.675,-1.65 -0.694,-1.646 -0.71,-1.635 -0.721,-1.619 -0.725,-1.6 -0.725,-1.6 -0.725,-1.175 -0.729,-1.156 -0.74,-1.14 -0.756,-1.129 -0.775,-1.125 -0.775,-1.125
  Top Layer region: 0.375,-1.6 0.379,-1.619 0.39,-1.635 0.406,-1.646 0.425,-1.65 0.425,-1.65 0.675,-1.65 0.694,-1.646 0.71,-1.635 0.721,-1.619 0.725,-1.6 0.725,-1.6 0.725,-1.175 0.729,-1.156 0.74,-1.14 0.756,-1.129 0.775,-1.125 0.775,-1.125 1.1,-1.125 1.119,-1.121 1.135,-1.11 1.146,-1.094 1.15,-1.075 1.15,-1.075 1.15,-0.925 1.146,-0.906 1.135,-0.89 1.119,-0.879 1.1,-0.875 1.1,-0.875 0.425,-0.875 0.406,-0.879 0.39,-0.89 0.379,-0.906 0.375,-0.925 0.375,-0.925
  Top Layer region: 0.375,0.925 0.375,1.6 0.379,1.619 0.39,1.635 0.406,1.646 0.425,1.65 0.425,1.65 0.675,1.65 0.694,1.646 0.71,1.635 0.721,1.619 0.725,1.6 0.725,1.6 0.725,1.175 0.729,1.156 0.74,1.14 0.756,1.129 0.775,1.125 0.775,1.125 1.1,1.125 1.119,1.121 1.135,1.11 1.146,1.094 1.15,1.075 1.15,1.075 1.15,0.925 1.146,0.906 1.135,0.89 1.119,0.879 1.1,0.875 1.1,0.875 0.425,0.875 0.406,0.879 0.39,0.89 0.379,0.906 0.375,0.925
  Top Layer region: -1.15,0.925 -1.15,1.075 -1.146,1.094 -1.135,1.11 -1.119,1.121 -1.1,1.125 -1.1,1.125 -0.775,1.125 -0.756,1.129 -0.74,1.14 -0.729,1.156 -0.725,1.175 -0.725,1.175 -0.725,1.6 -0.721,1.619 -0.71,1.635 -0.694,1.646 -0.675,1.65 -0.675,1.65 -0.425,1.65 -0.406,1.646 -0.39,1.635 -0.379,1.619 -0.375,1.6 -0.375,1.6 -0.375,0.925 -0.379,0.906 -0.39,0.89 -0.406,0.879 -0.425,0.875 -0.425,0.875 -1.1,0.875 -1.119,0.879 -1.135,0.89 -1.146,0.906 -1.15,0.925
  body extent -1,-1.5 1,1.5, height 1
SM_RADIAL_D8 [mm] "6.3 x 7.7mm:  Panasonic D8"
  rect 3.2x1.6 smd: 1(-2.5,0) 2(2.5,0)
  silkscreen extent -3.4,-3.4 3.4,3.4, body extent -3.4,-3.4 3.4,3.4, height 8.01
SMB-Bi [mil] "Molded Diode, 2-Leads, Body 5.4x3.6mm, IPC Medium Density, based on OnSemi component dimensions"
  rect 85x107.99 smd: 1(-87.01,0) 2(87.01,0)
  silkscreen extent -125,-79 125,79, body extent -104,-73 104,73, height 89
SOD-123F [mm] "NXP recommended land pattern"
  rect 1.2x1.2 smd paste-0.05: 1(-1.4,0) 2(1.4,0)
  silkscreen extent -2.64,-1.12 2.01,1.12, body extent -1.8,-0.85 1.8,0.85, height 1.2
SOD-123FL [mm] "Copied from SOD-123"
  rect 0.915x1.22 smd: 1(-1.637,0) 2(1.637,0)
  silkscreen extent -2.74,-1.16 1.68,1.16, body extent -1.9,-0.9 1.9,0.9, height 1
TSW-102-07-G-S [mm] "Samtec 100mil, 1x2, 230 mil above insulator"
  rrect50% 1.65x1.65 hole 1.016: 1(-1.27,0)
  round 1.65 hole 1.016: 2(1.27,0)
  body extent -2.54,-1.27 2.54,1.27, height 8.38
TSW-103-07-G-S [mm] "Samtec 100mil, 1x3, 230 mil above insulator"
  rrect50% 1.65x1.65 hole 1.016: 1(-2.54,0)
  round 1.65 hole 1.016: 2(0,0) 3(2.54,0)
  body extent -3.81,-1.27 3.81,1.27, height 8.38
TSW-108-07-G-D [mm] "Samtec 100mil, 2x8, 230 mil above insulator"
  rrect6% 1.65x1.65 hole 1.016: 1(-8.89,-1.27)
  round 1.65 hole 1.016: 2(-8.89,1.27) 3(-6.35,-1.27) 4(-6.35,1.27) 5(-3.81,-1.27) 6(-3.81,1.27) 7(-1.27,-1.27) 8(-1.27,1.27) 9(1.27,-1.27) 10(1.27,1.27) 11(3.81,-1.27) 12(3.81,1.27) 13(6.35,-1.27) 14(6.35,1.27) 15(8.89,-1.27) 16(8.89,1.27)
  silkscreen extent -11.19,-2.54 10.16,2.54, body extent -10.16,-2.54 10.16,2.54, height 8.38
TSW-110-07-G-D [mm] "Samtec 100mil, 2x10, 230 mil above insulator"
  rrect6% 1.65x1.65 hole 1.016: 1(-11.43,-1.27)
  round 1.65 hole 1.016: 2(-11.43,1.27) 3(-8.89,-1.27) 4(-8.89,1.27) 5(-6.35,-1.27) 6(-6.35,1.27) 7(-3.81,-1.27) 8(-3.81,1.27) 9(-1.27,-1.27) 10(-1.27,1.27) 11(1.27,-1.27) 12(1.27,1.27) 13(3.81,-1.27) 14(3.81,1.27) 15(6.35,-1.27) 16(6.35,1.27) 17(8.89,-1.27) 18(8.89,1.27) 19(11.43,-1.27) 20(11.43,1.27)
  silkscreen extent -13.72,-2.54 12.7,2.54, body extent -12.7,-2.54 12.7,2.54, height 8.38
Wurth_691101710002 [mm] "Terminal Block, 5 mm, 2x1, TH"
  rect 1.8x1.8 hole 1.3: 1(-2.5,0)
  round 1.8 hole 1.3: 2(2.5,0)
  silkscreen extent -5,-4.5 5.6,5, body extent -5.6,-4 5.6,5, height 12.5
XAL1010 [mm] "COILCRAFT"
  rect 2.38x11.31 smd: 1(-3.325,0) 2(3.325,0)
  silkscreen extent -5.3,-6 5.3,6, body extent -5.25,-5.9 5.25,5.9, height 10
XAL1060 [mm] "COILCRAFT"
  rect 2.39x11 smd: 1(-3.325,0) 2(3.325,0)
  silkscreen extent -5.3,-6 5.3,6, body extent -5.25,-5.9 5.25,5.9, height 6
XAL5030 [mil] "Coilcraft XAL5030 12/12/11"
  rect 46x183 smd: 1(-65,0) 2(65,0)
  silkscreen extent -108,-112 108,112, body extent -108,-112 108,112, height 122
XAL6060 [mm] "Coilcraft recommended land pattern Document 887-4 Revised 01/14/18"
  rrect7% 1.43x5.5 smd: 1(-2.019,0) 2(2.019,0)
  body extent -3.28,-3.38 3.28,3.38, height 6.11
XEL4020 [mm] "SMD, 2-Leads, Body 4x4mm, Pitch 2.37mm"
  rrect10% 0.98x3.4 smd: 1(-1.185,0) 2(1.185,0)
  body extent -2.15,-2.15 2.15,2.15, height 2.1
XPL2010 [mm] "Coilcraft recommended land pattern Document 646-2 Revised 3/28/11"
  rect 1.04x2.2 smd: 1(-0.725,0) 2(0.725,0)
  silkscreen extent -1.52,-1.4 1.52,1.4, body extent -1.05,-1.1 1.05,1.1, height 1

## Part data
C1 C6 C8 C10 C11 C19 C26 C33 C34 C61 C62 C63: library part CMP-0006675-2, "CAP, CERM, 0.1 uF, 50 V, +/- 20%, X7R, 0402", Cap_Case=0402, Manufacturer=MuRata, Supplier Part Number 1=490-10701-1-ND, TempCo=X7R, Tolerance_%=20%, Value1=Unknown, Value2=50V, ValueDisplayed=0.1uF
C2 C3 C4 C5: library part CMP-0008811-2, "CAP, CERM, 22 uF, 10 V, +/- 10%, X7R, AEC-Q200 Grade 1, 1206", Cap_Case=1206, Manufacturer=MuRata, TempCo=X7R, Tolerance_%=10%, Value1=Unknown, Value2=10V, ValueDisplayed=22uF
C7 C56 C57 C58: library part CMP-0006639-2, "CAP, CERM, 0.01 uF, 16 V, +/- 10%, X7R, 0402", Cap_Case=0402, Manufacturer=MuRata, Supplier Part Number 1=490-1313-1-ND, TempCo=X7R, Tolerance_%=10%, Value1=Unknown, Value2=16V, ValueDisplayed=0.01uF
C9: library part CMP-0007405-4, "CAP, CERM, 1 uF, 25 V, +/- 10%, X7R, 0603", Cap_Case=0603, Manufacturer=MuRata, Supplier Part Number 1=490-5307-1-ND, TempCo=X7R, Tolerance_%=10%, Value1=Unknown, Value2=25V, ValueDisplayed=1uF
C12: library part CMP-0011185-2, "CAP, AL, 47 uF, 50 V, +/- 20%, 0.68 ohm, AEC-Q200 Grade 2, SMD", Cap_Case=D8, Manufacturer=Panasonic, Supplier Part Number 1=PCE3816CT-ND, Tolerance_%=20%, Value1="0.68 ohm", Value2=50V, ValueDisplayed=47uF
C13 C14 C17 C27 C28 C29 C30 C31 C32: library part CMP-0009226-3, "CAP, CERM, 10 uF, 50 V, +/- 10%, X7R, 1210", Cap_Case=1210, Manufacturer=MuRata, Supplier Part Number 1=490-6544-1-ND, TempCo=X7R, Tolerance_%=10%, Value1=Unknown, Value2=50V, ValueDisplayed=10uF
C15: library part CMP-0087258-1, "Cap Aluminum Lytic 220uF 50V 20% (12.5 X 13.5mm) SMD 0.23 Ohm 600mA 2000h 125C T/R", Manufacturer="Panasonic Electronic Components", Tolerance_%=20%
C16: library part CMP-0006648-2, "CAP, CERM, 0.22 uF, 16 V, +/- 10%, X7R, 0402", Cap_Case=0402, Manufacturer=MuRata, Supplier Part Number 1=490-5418-1-ND, TempCo=X7R, Tolerance_%=10%, Value1=Unknown, Value2=16V, ValueDisplayed=0.22uF
C18: library part CMP-0007445-4, "CAP, CERM, 0.22 uF, 50 V, +/- 10%, X7R, 0603", Cap_Case=0603, Manufacturer=MuRata, Supplier Part Number 1=490-12546-1-ND, TempCo=X7R, Tolerance_%=10%, Value1=Unknown, Value2=50V, ValueDisplayed=0.22uF
C20 C21: library part CMP-0009219-2, "CAP, CERM, 22 uF, 10 V, +/- 10%, X7R, 1210", Cap_Case=1210, Manufacturer=MuRata, Supplier Part Number 1=490-11653-1-ND, TempCo=X7R, Tolerance_%=10%, Value1="0.002 ohm", Value2=10V, ValueDisplayed=22uF
C22: library part CMP-0006458-2, "CAP, CERM, 39 pF, 50 V, +/- 5%, C0G/NP0, 0402", Cap_Case=0402, Manufacturer=MuRata, Supplier Part Number 1=14T3296, TempCo=C0G/NP0, Tolerance_%=5%, Value1=Unknown, Value2=50V, ValueDisplayed=39pF
C23: library part CMP-0008313-2, "CAP, CERM, 1 uF, 10 V, +/- 10%, X7R, 0805", Cap_Case=0805, Manufacturer=MuRata, Supplier Part Number 1=490-1695-1-ND, TempCo=X7R, Tolerance_%=10%, Value1="0.007 ohm", Value2=10V, ValueDisplayed=1uF
C24 C25: library part CMP-0064994-1, "CAP, Polymer Hybrid, 100 uF, 50 V,+/- 20%, 0.028 ohm, AEC-Q200 Grade 1, D10xL10.2mm SMD", Cap_Case=10x10.2mm, Manufacturer=Panasonic, Supplier Part Number 1=P15462CT-ND, Tolerance_%=20%, Value1="0.028 ohm", Value2=50V, ValueDisplayed=100uF
C35 C36: library part CMP-0009221-2, "CAP, CERM, 47 uF, 10 V, +/- 20%, X7R, 1210", Cap_Case=1210, Manufacturer=MuRata, Supplier Part Number 1=490-6543-1-ND, TempCo=X7R, Tolerance_%=20%, Value1=Unknown, Value2=10V, ValueDisplayed=47uF
C37 C41: library part CMP-0086437-1, "Cap Aluminum Polymer 470uF 16VDC 20% (10 X 10mm) SMD 0.018 Ohm 2600mA 5000h 105C Automotive T/R", Manufacturer="United Chemi-Con", Tolerance_%=20%
C38 C39: library part CMP-0009189-2, "CAP, CERM, 10 uF, 10 V, +/- 20%, X7R, 1210", Cap_Case=1210, Manufacturer=MuRata, TempCo=X7R, Tolerance_%=20%, Value1=Unknown, Value2=10V, ValueDisplayed=10uF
